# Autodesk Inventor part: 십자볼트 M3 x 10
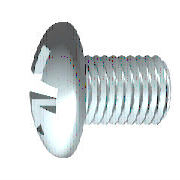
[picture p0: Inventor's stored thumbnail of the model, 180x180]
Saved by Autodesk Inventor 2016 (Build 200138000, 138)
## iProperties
IsCustomPart: 0
Created: 2012-02
Part Number: 십자볼트 M3 x 10
Material: 스테인리스강
Description: 십자 오목 머리 나사
Document SubType Name: Modeling
Standard: KS B 1023
Designer: mduedu
Standards Organization: KS
Language: ko-KR
Size Designation: A  M 3 x 10 - H
Categories: <MemberInstance><Categories><Category DisplayName="조임쇠" InternalName="e4da775c-781d-43d5-af7c-5136215cf5a6" Mnemonic="FSTN"><Category DisplayName="볼트" InternalN
Density: 1 g/cm^3
Appearance: 반광택
Author: mduedu
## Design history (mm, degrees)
workplane "Work Plane3"
sketch "스케치2"
  geometry: L1 (-3.72, 0)-(3.72, 0) reference; L2 (0, -3.72)-(0, 3.72) reference; L3 (0, 1.5)-(0, 0); L4 (0, 0)-(1.5, 0); L5 (0, 0)-(1.879, 1.879); L6 (0.253, 1.479)-(0.261, 0.456); L7 (1.479, 0.253)-(0.456, 0.261); L8 (0.253, -1.479)-(0.261, -0.456); L9 (1.479, -0.253)-(0.456, -0.261); L10 (-0.253, 1.479)-(-0.261, 0.456); L11 (-1.479, 0.253)-(-0.456, 0.261); L12 (-1.479, -0.253)-(-0.456, -0.261); L13 (-0.253, -1.479)-(-0.261, -0.456); A1 r 0.45 centre (0, 0) between (0.45, 0) and (0, 0.45); A2 r 1.5 centre (0, 0) between (1.5, 0) and (1.479, 0.253); A3 r 1.5 centre (0, 0) between (0.253, 1.479) and (0, 1.5); A4 r 1.5 centre (0, 0) between (1.479, 0.253) and (0.253, 1.479); A5 r 1.5 centre (0, 0) between (0, -1.5) and (0.253, -1.479); A6 r 1.5 centre (0, 0) between (0.253, -1.479) and (1.479, -0.253); A7 r 1.5 centre (0, 0) between (1.479, -0.253) and (1.5, 0); A8 r 1.5 centre (0, 0) between (-1.479, 0.253) and (-1.5, 0); A9 r 1.5 centre (0, 0) between (-0.253, 1.479) and (-1.479, 0.253); A10 r 1.5 centre (0, 0) between (0, 1.5) and (-0.253, 1.479); A11 r 1.5 centre (0, 0) between (-1.5, 0) and (-1.479, -0.253); A12 r 1.5 centre (0, 0) between (-1.479, -0.253) and (-0.253, -1.479); A13 r 1.5 centre (0, 0) between (-0.253, -1.479) and (0, -1.5); A14 r 0.525 centre (0, 0) between (0.525, 0) and (0, 0.525); A15 r 0.197 centre (0.457, 0.457) between (0.261, 0.456) and (0.456, 0.261); A16 r 0.197 centre (0.457, -0.457) between (0.456, -0.261) and (0.261, -0.456); A17 r 0.197 centre (-0.457, 0.457) between (-0.456, 0.261) and (-0.261, 0.456); A18 r 0.197 centre (-0.457, -0.457) between (-0.261, -0.456) and (-0.456, -0.261); 1 further point
  constraints: 38 point on circle, 22 end point, 19 symmetric about line, 18 centre point, 4 coincident, 3 collinear, 3 point on line, 3 tangent, 1 perpendicular, 21 other
  dimensions: "d4" = 45 deg angle of L5 L4; "d5" = 0.9 diameter of A1 (= 0.3 x SDM); "d6" = 3 diameter of A4 (= SDM); "d7" = 0.2525 distance from line of L6.start L3 (= 0.5 x SBR); "d14" = 1.05 diameter of A14 (= 0.35 x SDM)
extrude "슬롯" join sketch "스케치2" taper "d15" = 5 deg; stored distance "d54" = 10
revolve "절단부" stored, may be unused: angle "d56" = 90 deg
revolve "본체" stored, may be unused: angle "d18" = 90 deg
workplane "Work Plane1"
body "Solid1"
sketch "스케치1"
  geometry: L1 (10, 0)-(10, 1.5); L2 (10, 1.5)-(1, 1.5); L3 (3.962, 5.08)-(3.962, 5.08); L4 (-2.4, 0)-(-2.4, 2.59); L5 (-2.2, 1.4)-(-1.036, 0.82); L6 (-1.036, 0.82)-(-0.6, 0); L7 (-0.6, 0)-(10, 0); L8 (-5.105, 0)-(12.517, 0) reference; L9 (0, -1.016)-(0, 6.096) reference; L10 (-2.2, 1.4)-(-2.4, 1.5); L11 (-1.636, 2.657)-(-2.4, 2.59); L12 (-1.636, 2.657)-(0, 2.8); L13 (0, 2.8)-(0, 1.347); L14 (0, 1.347)-(0.693, 1.347); L15 (0.693, 1.347)-(1, 1.5); L16 (1, 1.5)-(0, 1.5); A1 r 5 centre (2.6, 0) between (-1.636, 2.657) and (-2.4, 0)
  constraints: 28 end point, 5 point on line, 4 collinear, 4 point on circle, 3 parallel, 2 perpendicular, 1 centre point, 1 horizontal, 1 tangent
  dimensions: "d1" = 3 diameter of L2 L7 (= GD); "d2" = 1.8 distance from line of L6.end L4 (= STI); "d11" = 3 diameter of L10.end L7 (= SDM); "d12" = 62 deg angle of L6 L7; "d13" = 26.5 deg angle of L5 L7; "d17" = 5.6 diameter of L12.end L7 (= KOD); "d19" = 5 deg angle of L12 L7 (= KEWI); "d20" = 2.4 distance between parallel lines of L4 L13 (= KOH); "d21" = 5 radius of A1 (= KR); "d23" = 2.6935 diameter of L14 L7 (= BDM); "d24" = 9 distance of L1.end L2.end (= GEL); "d25" = 0.30673 horizontal distance of L14.end L2.end (= GAL); "d28" = 10 distance between parallel lines of L1 L13 (= NLG)
fillet "모깎기1" dims "d29" = 1.2 (= RR)
fillet "모깎기2" dims "d16" = 0.101 (= 0.2 x SBR)
feature "스레드" dims "d8" = 9 (= GEL), "d9" = 0
chamfer "모따기1" distance "d26" = 0.30673 (= -0.5 x SPD + 0.5 x GD); stored, may be unused: second distance "d27" = 0.30683 (computed from GUL), angle "d78" = 45 deg
other parameters: "GD" = 3 (= NND) [user parameter; used in 2 equation terms], "NLG" = 10 [user parameter; used in 1 equation term], "GEL" = 9 [user parameter; used in 2 equation terms], "KOD" = 5.6 [user parameter; used in 1 equation term], "KOH" = 2.4 [user parameter; used in 2 equation terms], "SDM" = 3 [user parameter; used in 4 equation terms], "STI" = 1.8 [user parameter; used in 1 equation term], "SBR" = 0.505 [user parameter; used in 2 equation terms], "GAL" = 0.30673 (= 0.61345 x PTC) [user parameter; used in 1 equation term], "SPD" = 2.38655 (= NND - 1.2269 x PTC) [user parameter; used in 1 equation term], "KEWI" = 5 deg [user parameter; used in 1 equation term], "d3" = -2.4 (= -KOH), "d10" = 0, "KR" = 5 [user parameter; used in 1 equation term], "BDM" = 2.6935 [user parameter; used in 1 equation term], "GUL" = 0.30673 (= 0.61345 x PTC) [user parameter; used in 1 equation term], "RR" = 1.2 [user parameter; used in 1 equation term], "d79" = 0, "d80" = 0, "PTC" = 0.5 [user parameter; used in 5 equation terms], "THREADDIA" = 3 [user parameter; used in 1 equation term], "TOA" = 30 deg [user parameter], "NND" = 3 [user parameter; used in 2 equation terms], "GD1" = 2.38655 (= THREADDIA - 1.2269 x PTC) [user parameter]
